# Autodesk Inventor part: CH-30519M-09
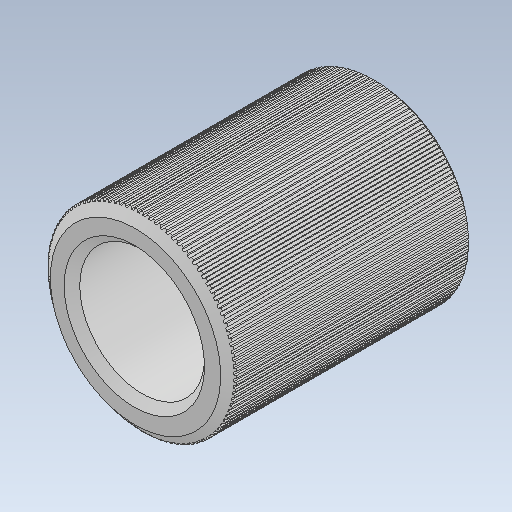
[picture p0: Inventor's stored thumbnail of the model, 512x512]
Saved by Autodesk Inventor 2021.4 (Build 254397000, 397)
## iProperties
Created: 2017-11
Part Number: CH-30519M-09
Material: Ogólny
Document SubType Name: Modeling
Designer: user
Density: 1 g/cm^3
Appearance: Domyślna
Author: user
Revision Number: ÈÎºÎ
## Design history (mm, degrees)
feature "µ¹½Ç1"
node "Bryła1"
